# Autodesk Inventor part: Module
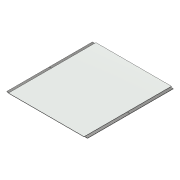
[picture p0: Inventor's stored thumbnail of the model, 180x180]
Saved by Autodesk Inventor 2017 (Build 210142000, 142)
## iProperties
Part Number: Module
Material: 一般
Document SubType Name: Modeling
Designer: kyushu-hep
Density: 1 g/cm^3
Appearance: 既定
Mass: 0.489782 g
Surface Area: 31.864 cm^2
Volume: 0.489782 cm^3
Author: kyushu-hep
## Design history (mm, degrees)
sketch "スケッチ1"
  geometry: L1 (-17.274, 15.65)-(20.836, 15.65); L2 (20.836, 15.65)-(20.836, -24.8); L3 (20.836, -24.8)-(-17.274, -24.8); L4 (-17.274, -24.8)-(-17.274, 15.65); 1 further point
  constraints: 8 end point, 2 parallel, 1 horizontal, 1 perpendicular
  dimensions: "d0" = 38.11 distance of L1.start L1.end; "d1" = 40.45 distance of L3.end L1.start
extrude "押し出し1" new body sketch "スケッチ1" distance "d2" = 0.175; taper "d3" = 0 deg
sketch "スケッチ2"
  geometry: L1 (-16.024, 16.019)-(19.586, 16.019); L2 (19.586, 16.019)-(19.586, -25.169); L3 (19.586, -25.169)-(-16.024, -25.169); L4 (-16.024, -25.169)-(-16.024, 16.019); L5 (-17.274, -24.8)-(20.836, -24.8) reference; L6 (-17.274, -24.8)-(-17.274, 15.65) reference; 1 further point
  constraints: 8 end point, 2 parallel, 1 horizontal, 1 perpendicular
  dimensions: "d4" = 35.61 distance of L1.start L1.end; "d5" = 41.188 distance of L3.end L1.start; "d6" = 0.369 distance between parallel lines of L3 L5; "d7" = 1.25 distance between parallel lines of L6 L4
extrude "押し出し2" join sketch "スケッチ2" distance "d8" = 0.15; taper "d9" = 0 deg
sketch "スケッチ5"
  geometry: L1 (-17.274, -4.775)-(-16.274, -4.775); L2 (-16.274, -4.775)-(-16.274, -4.825); L3 (-16.274, -4.825)-(-17.274, -4.825); L4 (-17.274, -4.825)-(-17.274, -4.775); L5 (20.836, -24.8)-(20.836, 15.65) reference; L6 (20.836, 15.65)-(19.586, 15.65) reference; L7 (19.836, -4.825)-(20.836, -4.825); L8 (20.836, -4.825)-(20.836, -4.875); L9 (20.836, -4.875)-(19.836, -4.875); L10 (19.836, -4.875)-(19.836, -4.825); L11 (-17.274, 15.65)-(-17.274, -24.8) reference; 1 further point
  constraints: 16 end point, 4 parallel, 2 horizontal, 2 perpendicular, 1 collinear, 1 point on line
  dimensions: "d19" = 1 distance of L2.end L3.end; "d20" = 0.05 distance of L3.end L1.start; "d21" = 20.425 distance between parallel lines of L6 L1; "d22" = 0.05 distance of L9.end L7.start; "d23" = 0 distance between parallel lines of L7 L3
extrude "押し出し4" join sketch "スケッチ5" distance "d24" = 0.05; taper "d25" = 0 deg
node "ソリッド1"
